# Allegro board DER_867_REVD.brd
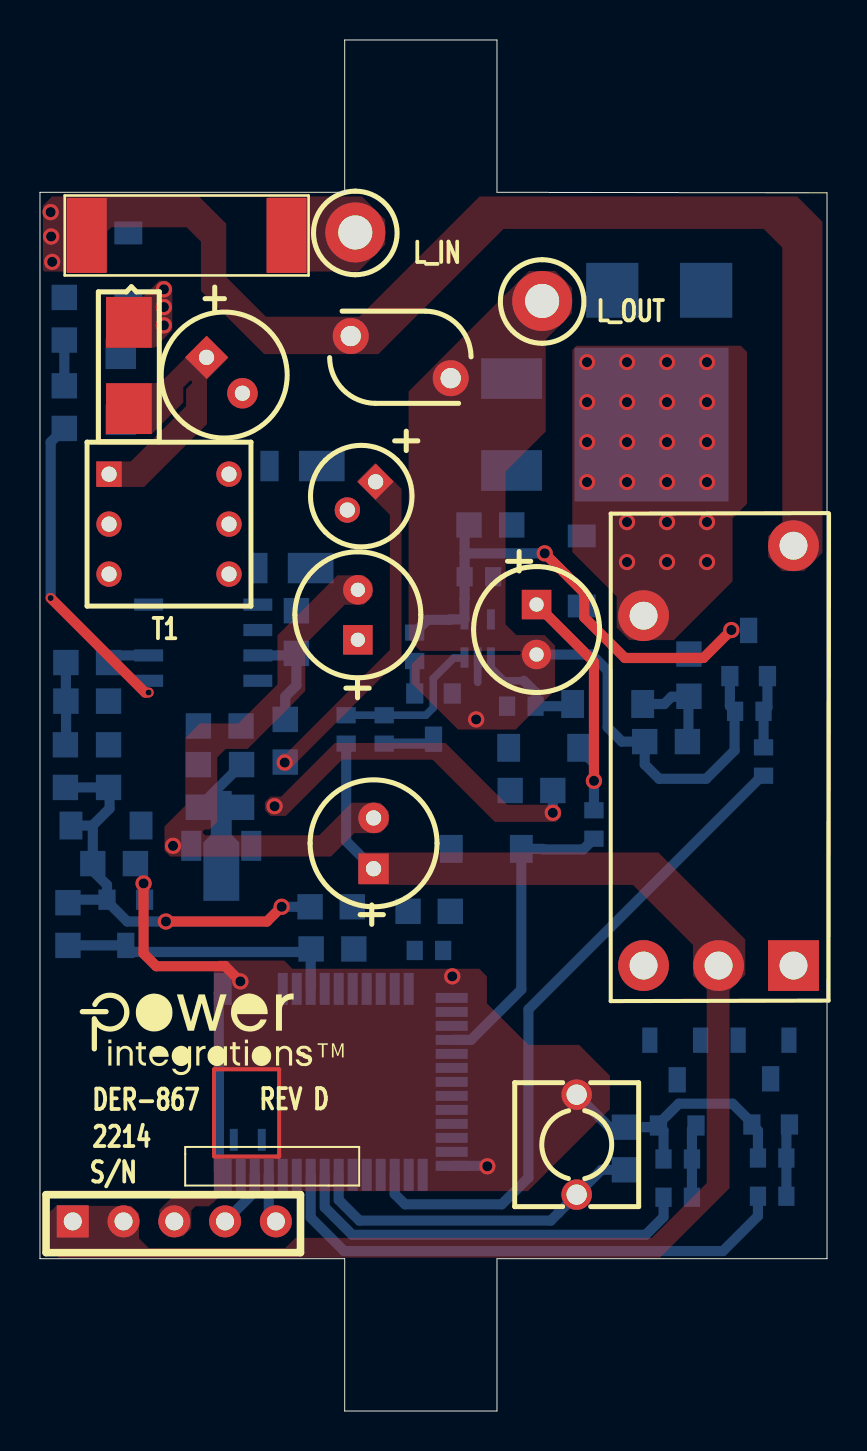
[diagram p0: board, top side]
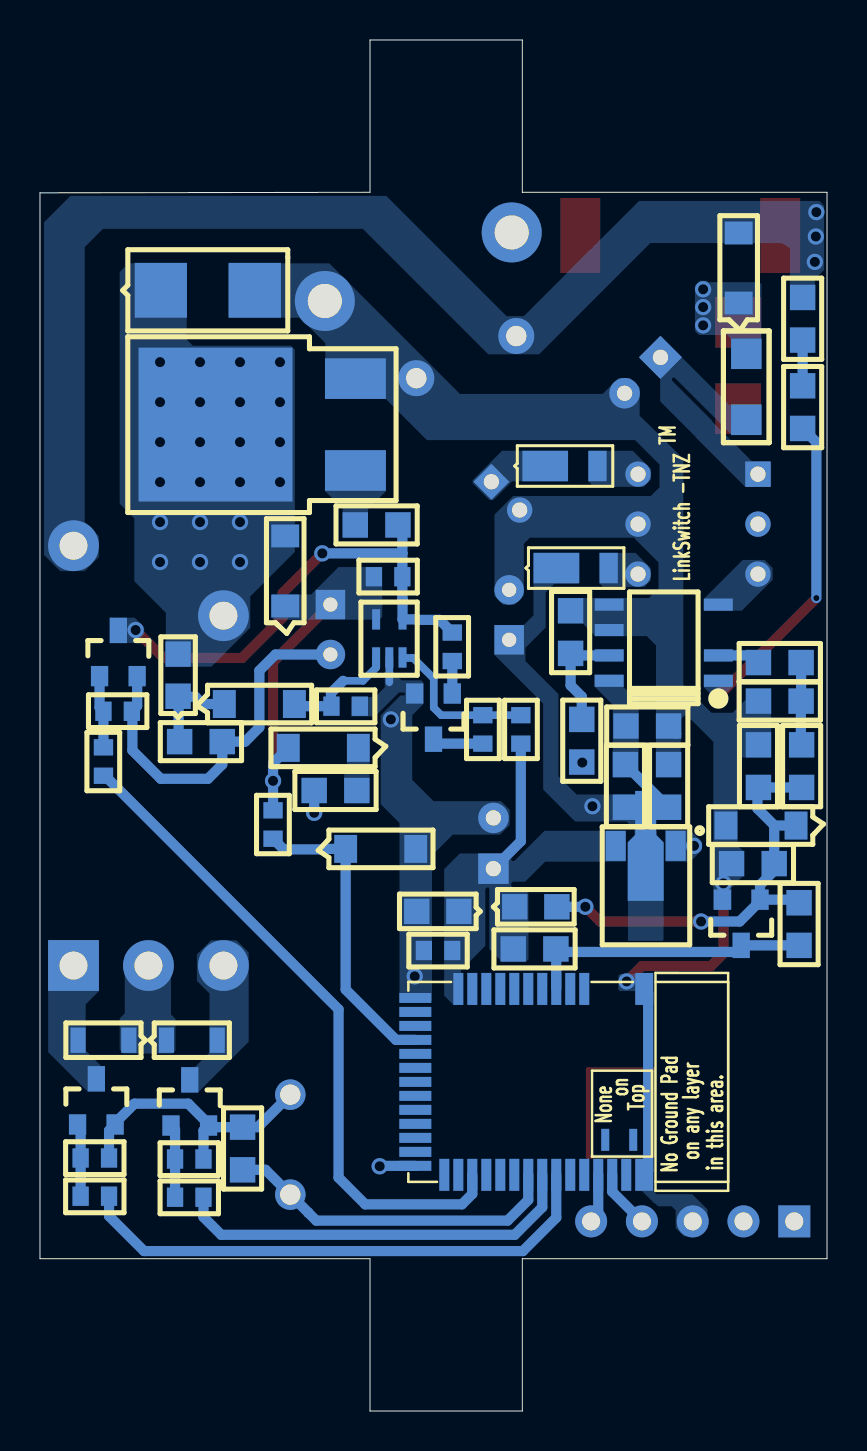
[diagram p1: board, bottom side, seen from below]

Outline 39.37 x 68.58 mm; copper layers: TOP, BOTTOM. Coordinates in mm from the lower left corner of the outline.
Outline path: 0,60.96 0,7.62 15.24,7.62 15.24,0 22.86,0 22.86,7.62 39.37,7.62 39.37,60.93 22.86,60.96 22.86,68.58 15.24,68.58 15.24,60.96 0,60.96

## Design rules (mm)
constraint set DEFAULT: min track width 0.508

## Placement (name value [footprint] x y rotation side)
C1  2.2 uF  [PIPOLCAP6P3X16P5D030]  8.33 52.7 315 top
C5  100 nF  [PISMC0805]  12.83 37.9 90 bottom
C6  56 uF  [PIPOLCAPCLYD200LS80030]  16.79 46.48 225 top
C7  10 uF  [PISMC0603]  20.17 23.04 180 bottom
C8  100 pF  [PISMC0805]  1.3 35.51 0 bottom
C9  100 nF  [PISMC0805]  29.24 12.07 90 bottom
C12  100 nF  [PISMC0805]  30.25 33.48 0 bottom
C13  100 uf  [PIPOLCAPCLYD248LS098028]  24.84 39.09 270 top
C14  220 uF  [PIPOLCAPCLYD248LS098028]  15.9 39.83 90 top
C15  560 uF  [PIPOLCAPCYLD250LS100030]  16.69 27.13 90 top
C16  100 nF  [PISMC0805]  10.06 34.26 180 bottom
C17  100 pF  [PISMC0805]  3.43 31.19 90 bottom
D1  DFLS160-7  [PISMDDFLR120012]  13.56 42.16 0 bottom
D2  S1V-13-F  [PI_SM_SOD-123_12]  4.42 55.42 90 bottom
D3  DFLR1200-7  [PISMDDFLR120012]  14.12 47.27 0 bottom
D4  1N4148WS  [PISMDSOD323]  18.41 24.99 0 bottom
D7  B340LB-13-F  [PISMDO214AA12]  33.32 56.06 180 bottom
D8  SM4003PL-TP  [PI_SM_SOD-123_12]  27.1 40.27 90 bottom
D9  1N4148WS  [PISMDSOD323]  32.46 35.75 90 bottom
D10  SM4003PL-TP  [PI_SM_SOD-123_12]  23.44 33.17 0 bottom
D11  BAV16WS-7-F  [PISMSOD323]  34.92 18.55 0 bottom
D12  BAV16WS-7-F  [PISMSOD323]  33.05 18.55 180 bottom
D13  DNP  [PISMDSOD323]  15.62 25.22 180 bottom
F1  10 A  [PISMFUSE10P1X3P0]  2.34 58.8 0 top
J1  CON5  [PI_HDRF_1X5_HIROSE]  1.64 9.49 0 top
NOREF  -  []  0 7.62 90 top
NOREF#2  -  []  0 60.96 0 top
NOREF#3  -  []  15.24 0 90 top
NOREF#4  -  []  2.01 21.36 0 top
NOREF#5  -  []  15.24 68.58 0 top
NOREF#6  -  []  -228.6 -137.16 0 top
NOREF#7  -  []  -150.78 61.85 0 top
Q1  IPD036N04LGATMA1  [PISMDDPAK]  23.59 47.04 90 bottom
Q2  MMBT3904  [PISMSOT23123_1]  34.51 36.76 180 bottom
Q3  MMBT3904  [PISMSOT23123_1]  20.62 35.89 0 bottom
Q4  MMBT6427-7-F  [PISMSOT23123_1]  35.61 14.33 180 bottom
Q5  MMBT6427-7-F  [PISMSOT23123_1]  30.94 14.28 180 bottom
Q6  2N7002L  [PISMSOT23123_1]  5.23 25.58 0 bottom
R1  16 K  [PISMR1206]  4.04 49.58 90 bottom
R5  9.31 k  [PISMR0805]  10.08 30.2 90 bottom
R7  17.8 k  [PISMR0805]  7.92 32.33 270 bottom
R8  0.0  [PISMR0805]  3.43 37.44 180 bottom
R9  100 k  [PISMR0603]  27.71 30.05 270 bottom
R10  499 k  [PISMR0805]  1.22 55.7 270 bottom
R11  100 k  [PISMR0603]  34.77 35 0 bottom
R12  47  [PISMR0805]  23.6 44.32 180 bottom
R13  2 k  [PISMR0603]  21.24 41.73 0 bottom
R14  100 k  [PISMR0603]  18.75 38.94 270 bottom
R15  15 k  [PISMR0603]  17.22 33.38 90 bottom
R16  10 k  [PISMR0603]  15.32 33.38 90 bottom
R17  634 k  [PISMR0603]  24.79 35.26 180 bottom
R18  47  [PISMR0805]  23.52 31.04 0 bottom
R19  1 k  [PISMR0603]  37.34 10.74 180 bottom
R20  470 k  [PISMR0603]  37.34 12.66 180 bottom
R21  1 k  [PISMR0603]  32.61 10.69 180 bottom
R22  470 k  [PISMR0603]  32.61 12.61 180 bottom
R24  1 k  [PISMR0603]  36.2 33.2 270 bottom
R25  0.0  [PISMR0805]  1.27 33.32 270 bottom
R26  49.9 k  [PISMR0805]  12.27 34.59 270 bottom
R27  499 k  [PISMR0805]  1.22 51.28 270 bottom
R28  100 k  [PISMR0805]  15.7 23.11 180 bottom
R29  499 k  [PISMR0805]  2.64 27.38 0 bottom
R30  0  [PISMR0805]  1.4 23.29 90 bottom
RL1  SPST NO  [PI_RLY-PANASONIC_2COIL]  37.69 22.28 90 top
RV1  275 Vac  [PI_DISC276X181_LS200X83D040]  15.54 53.77 0 top
SW1  SPST  (NO)  [PI_SWITCH_SPST_TL59]  26.85 13.32 180 top
T1  EE8.3  [PI_BOBBIN_EE8_3_V6P]  3.45 46.86 0 top
TP1  RED  [PITPKEYSTONE125X125]  15.77 58.95 0 top
TP2  RED  [PITPKEYSTONE125X125]  25.12 55.52 0 top
U1  LNK3302D  [PISMSO8_NOP3]  5.44 36.53 90 bottom
U4  MDBT42Q  [PI_MOD_RAYTAC_MDBT42Q]  9.14 21.46 270 bottom
U6  TLV1701AIDCKT  [PISMSC705]  22.56 37.69 180 bottom
U7  MCP1703T-3002E/MB  [PI_SM_SOT89-3]  7.57 28.27 0 bottom
VR1  SMAZ12-13-F  [PISMDO214AC12]  4.45 54.46 270 top
VR2  MMSZ4683T1G  [PI_SM_SOD-123_12]  24.08 28.12 180 bottom
VR3  MMSZ4693T1G  [PI_SM_SOD-123_12]  30.15 35.36 180 bottom
VR4  MMSZ4693T1G  [PI_SM_SOD-123_12]  1.55 29.29 0 bottom

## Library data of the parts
C1 = CAP POL: alternate symbols: (pipolcap6p3x16p5d030H)
C5 C8 C9 C16 C17 = CAP NP
C6 C15 = CAP POL
C7 = CAP NP: room: 3
C12 = CAP NP: room: 1
C13 = CAP POL: alternate symbols: (pipolcapclyd248ls098028_h)
C14 = CAP POL: alternate symbols: (pipolcapclyd6p3x9mm_h)
D1 = DIODE SCHOTTKY
D2 D3 D8-D10 = DIODE
D4 D11-D13 = DIODE: room: 2
D7 = DIODE SCHOTTKY: room: 1
F1 = FUSE
J1 = CON5
Q1 = FET_N_GDS: alternate symbols: (pi_sm_d_pak_1); room: 1
Q2 Q3 = NPN_BEC: room: 1
Q4 Q5 = NPN DAR_BEC: room: 2
Q6 = FET_N_GSD
R1 = R: alternate symbols: (pismr1206_1)
R5 R7 R26 R28 R30 = R
R8 = R: alternate symbols: (pismr0805_1); tolerance: 1%
R9 R19-R22 = R: room: 2
R10-R12 R14-R18 R24 R27 = R: room: 1
R13 = R: alternate symbols: (pismr0603_1); room: 1
R25 = R: alternate symbols: (pismr0805_1)
R29 = R: tolerance: 1%
RL1 = RELAY SPST_PANASONIC_DOUBLECOIL: room: 2
RV1 = VARISTOR
SW1 = SW SPST
T1 = BEE8_3_6P
TP1 TP2 = TESTPOINT: room: 2
U1 = LNK-TNZ
U4 = Mod_Raytac_MDBT42Q
U6 = TLV1701a
U7 = LM78LXX_GIO
VR1 VR3 VR4 = DIODE_ZENER
VR2 = DIODE_ZENER: room: 3

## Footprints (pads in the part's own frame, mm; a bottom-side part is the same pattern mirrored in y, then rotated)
PI_BOBBIN_EE8_3_V6P
  rect 1.27x1.27 hole 0.762: 1(0,0)
  round 1.27 hole 0.762: 2(0,-2.5) 3(0,-5) 4(6,-5) 5(6,-2.5) 6(6,0)
PI_DISC276X181_LS200X83D040
  round 1.8 hole 1.016: 1(0,0) 2(5.001,-2.108)
PI_HDRF_1X5_HIROSE
  rect 1.6x1.6 hole 0.9: 1(0,0)
  round 1.6 hole 0.9: 2(2.54,0) 3(5.08,0) 4(7.62,0) 5(10.16,0)
PI_MOD_RAYTAC_MDBT42Q
  rect 1.6x0.899 smd: 1(0.35,0) 39(9.65,0)
  rect 1.6x0.5 smd: 2(0.35,-3) 3(0.35,-3.7) 4(0.35,-4.4) 5(0.35,-5.1) 6(0.35,-5.8) 7(0.35,-6.5) 8(0.35,-7.2) 9(0.35,-7.9) 10(0.35,-8.6) 11(0.35,-9.3) 25(9.65,-10) 26(9.65,-9.3) 27(9.65,-8.6) 28(9.65,-7.9) 29(9.65,-7.2) 30(9.65,-6.5) 31(9.65,-5.8) 32(9.65,-5.1) 33(9.65,-4.4) 34(9.65,-3.7) 35(9.65,-3) 36(9.65,-2.3) 37(9.65,-1.6) 38(9.65,-0.9)
  rect 0.5x1.6 smd: 12(0.8,-11.45) 13(1.5,-11.45) 14(2.2,-11.45) 15(2.9,-11.45) 16(3.6,-11.45) 17(4.3,-11.45) 18(5,-11.45) 19(5.7,-11.45) 20(6.4,-11.45) 21(7.1,-11.45) 22(7.8,-11.45) 23(8.5,-11.45) 24(9.2,-11.45)
  rect 1.1x0.399 smd: 40(7.9,-0.55) 41(7.9,-1.95)
PI_RLY-PANASONIC_2COIL
  rect 2.54x2.54 hole 1.397: 1(0,0)
  round 2.54 hole 1.397: 3(21.001,0) 5(17.501,7.501) 6(0,7.501) 7(0,3.749)
PI_SM_SOD-123_12
  rect 1.143x1.397 smd: 1(0,0) 2(3.505,0)
PI_SM_SOT89-3
  rect 1.001x1.501 smd: 1(0,0) 3(3,0)
  custom 0.45x0.45 smd: 2(1.501,0)
PI_SWITCH_SPST_TL59
  round 1.524 hole 1.016: 1(0,-2.5) 2(0,2.5)
PIPOLCAP6P3X16P5D030
  rect 1.524x1.524 hole 0.762: 1(0,0)
  round 1.524 hole 0.762: 2(2.54,0)
PIPOLCAPCLYD200LS80030
  rect 1.27x1.27 hole 0.762: 1(0,0)
  round 1.27 hole 0.762: 2(2,0)
PIPOLCAPCLYD248LS098028
  rect 1.473x1.473 hole 0.711: 1(-1.25,0)
  round 1.473 hole 0.711: 2(1.25,0)
PIPOLCAPCYLD250LS100030
  rect 1.524x1.524 hole 0.762: 1(0,0)
  round 1.524 hole 0.762: 2(2.54,0)
PISMC0603
  rect 0.813x0.965 smd: 1(0,0) 2(1.422,0)
PISMC0805
  rect 1.27x1.27 smd: 1(0,0) 2(2.134,0)
PISMDDFLR120012
  rect 2.286x1.524 smd: 1(-0.025,0)
  rect 0.914x1.524 smd: 2(-2.642,0)
PISMDDPAK
  rect 2.032x3.048 smd: 1(0.005,0) 3(4.6,0)
  rect 7.699x7.699 smd: 2(2.301,7)
PISMDO214AA12
  rect 2.616x2.743 smd: 1(0,0) 2(4.699,0)
PISMDO214AC12
  rect 2.54x2.286 smd: 1(0,0) 2(4.318,0)
PISMDSOD323
  rect 1.27x1.27 smd: 1(0,0) 2(2.108,0)
PISMFUSE10P1X3P0
  rect 2x3.75 smd: 1(0,0) 2(10,0)
PISMR0603
  rect 0.813x0.965 smd: 1(0,0) 2(1.422,0)
PISMR0805
  rect 1.27x1.27 smd: 1(0,0) 2(2.134,0)
PISMR1206
  rect 1.524x1.524 smd: 1(0,0) 2(3.302,0)
PISMSC705
  rect 0.399x1.016 smd: 1(0,0) 2(0.66,0) 3(1.321,0) 4(1.321,1.905) 5(0,1.905)
PISMSO8_NOP3
  rect 0.61x1.448 smd: 1(0,0) 2(1.27,0) 4(3.81,0) 5(3.81,5.461) 6(2.54,5.461) 7(1.27,5.461) 8(0,5.461)
PISMSOD323
  rect 0.762x1.27 smd: 1(0,0) 2(2.54,0)
PISMSOT23123_1
  rect 0.864x1.016 smd: 1(-1.88,0) 2(0,0)
  rect 0.864x1.27 smd: 3(-0.94,2.286)
PITPKEYSTONE125X125
  round 3 hole 1.702: 1(0,0)

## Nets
3V: C7.2 C15.1 D4.1 D11.1 D12.1 D13.1 J1.1 J1.2 R16.1 R28.1 RL1.7 U4.11(VDD) U7.3(OUT)
ADC_STATUS: C13.1 D8.1 D10.2 R9.1 R13.2 U6.5
L_IN: F1.2 TP1.1
L_OUT: C1.2 C5.2 C6.2 C7.1 C8.2 C9.2 C12.1 C13.2 C14.2 C15.2 C16.2 C17.2 D4.2 D7.2 J1.3 Q1.3(S) Q2.2(EMITTER) Q3.2(EMITTER) Q4.2(E) Q5.2(E) Q6.2(S) R7.1 R11.1 R17.2 R20.2 R22.2 R29.2 RV1.2 SW1.1 T1.5 TP2.1 U1.5 U1.6 U4.1 U4.12 U4.24 U4.39 U6.2 U7.1 VR2.2 VR4.2
LDO_IN: C14.1 D1.1 R5.1 R18.2 U7.2
ON_OFF: C9.1 SW1.2 U4.31
RLY_OFF: R19.2 U4.33
RLY_ON: R21.2 U4.32
STATUS_ADC: R9.2 U4.15 VR2.1
SWDCLK: J1.5 U4.36
SWDIO: J1.4 U4.37
ZCD_IN: Q6.3 R28.2 R30.1 U4.4
ZCD_OUT: R24.2 U4.27
N48269: D7.1 D8.2 D9.2 Q1.2 RL1.5
N49650: R17.1 U6.1 VR3.2
N51578: Q2.3 R12.2 R13.1 R14.1 U6.4
N257317: R15.2 R16.2 U6.3
N372848: D11.2 Q4.3 RL1.1
N372944: D12.2 Q5.3 RL1.6
N414217: Q1.1 R12.1
N423761: Q5.1 R21.1 R22.1
N460853: D10.1 R18.1
N471353: C12.2 D9.1 VR3.1
N477862: Q2.1 R11.2 R24.1
N518037: Q3.3 R15.1
N525361: Q4.1 R19.1 R20.1
N526799: Q3.1 R14.2
N595771: D2.2 F1.1 R10.1 RL1.3(NO) RV1.1
N598020: C1.1 R1.1 T1.1 VR1.2
N632777: R10.2 R27.1
N682309: R27.2 U1.1
N682418: T1.3 U1.4
N687847: D3.2 T1.6
N687859: C6.1 D3.1 R26.2
N687971: D1.2 T1.4
N688873: C16.1 R5.2 R7.2 U1.8
N704755: C5.1 R26.1 U1.7
N705901: C17.1 D13.2 Q6.1 R25.2 R29.1 R30.2 VR4.1
N724784: R8.1 U1.2
N755538: C8.1 R8.2 R25.1
N772684: D2.1 R1.2 VR1.1

Pads without a net: T1 2; U4 2 3 5 6 7 8 9 10 13 14 16 17 18 19 20 21 22 23 25 26 28 29 30 34 35 38 40 41

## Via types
v1: diameter 0.813, hole 0.508, TOP to BOTTOM, 42 vias
v2: diameter 0.457, hole 0.305, TOP to BOTTOM, 2 vias

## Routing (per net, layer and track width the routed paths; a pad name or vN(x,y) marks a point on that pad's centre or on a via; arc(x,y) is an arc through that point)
3V: length 7.6
  BOTTOM w0.508: C15.1 15.32,28.5 R16.1 ; 34.47,22.81 RL1.7
ADC_STATUS: length 13.4
  TOP w0.508: v1(27.71,31.52) 27.71,37.47 C13.1
  BOTTOM w0.508: R9.1 v1(27.71,31.52) 27.71,32.41 D10.2
L_OUT: length 55.2
  TOP w0.508: v1(5.18,26.39) 5.18,22.89 5.82,22.25 9.26,22.25 v1(10.02,21.49)
  BOTTOM w0.381: U6.2 21.89,36.45
  BOTTOM w0.508: Q5.2 30.94,14.36 31.95,15.37 34.65,15.37 35.61,14.41 Q4.2 35.92,14.03 R20.2 ; Q5.2 31.19,14.03 R22.2 ; Q5.2 30.85,14.2 C9.2 28.47,14.2 SW1.1 ; C16.2 7.54,33.88 ; v1(22.38,12.24) 22.36,12.26 U4.24 ; C13.2 27.59,37.84 28.4,37.03 28.4,34.2 29.11,33.48 C12.1 30.25,32.34 30.97,31.62 33.32,31.62 34.75,33.05 34.75,34.98 R11.1 34.51,35.26 Q2.2 ; U4.1 8.95,20.92 8.95,12.01 U4.39
  vias: v1(6.65,28.27) v1(20.62,21.74) v1(21.82,34.59)
LDO_IN: length 1.1
  BOTTOM w0.508: v1(25.65,29.92) R18.2
  vias: v1(11.73,30.25)
ON_OFF: length 17
  BOTTOM w0.508: C9.1 28.09,12.07 SW1.2 25.95,9.93 25.95,9.92 25.55,9.53 15.98,9.53 14.94,10.56 U4.31
RLY_OFF: length 26.9
  BOTTOM w0.508: R19.2 35.92,9.75 34.16,8 15.21,8 13.54,9.67 U4.33
RLY_ON: length 20.5
  BOTTOM w0.508: U4.32 14.24,10.19 15.62,8.81 30.3,8.81 31.19,9.7 R21.2
STATUS_ADC: length 15.4
  BOTTOM w0.508: R9.2 27.18,28.09 25.18,28.09 25.16,28.12 VR2.1 24.08,21.08 21.56,18.56 U4.15
SWDCLK: length 2.5
  BOTTOM w0.508: J1.5 11.44,9.84 U4.36
SWDIO: length 2.9
  BOTTOM w0.508: J1.4 10.74,10.97 U4.37
ZCD_IN: length 14.3
  BOTTOM w0.508: R28.2 13.54,23.09 ; 13.54,23.09 U4.4 ; 13.54,23.09 13.41,22.96 4.62,22.96 Q6.3 R30.1
ZCD_OUT: length 33.4
  BOTTOM w0.508: U4.27 17.74,10.86 18.26,10.34 23.1,10.34 24.43,11.68 24.43,20.09 36.12,31.78 R24.2
N48269:
  vias: v1(27.36,52.47) v1(27.36,50.47) v1(27.36,48.47) v1(27.36,46.47) v1(29.36,52.47) v1(29.36,50.47) v1(29.36,48.47) v1(29.36,46.47) v1(29.36,44.47) v1(29.36,42.47) v1(31.36,52.47) v1(31.36,50.47) v1(31.36,48.47) v1(31.36,46.47) v1(31.36,44.47) v1(31.36,42.47) v1(33.36,52.47) v1(33.36,50.47) v1(33.36,48.47) v1(33.36,46.47) v1(33.36,44.47) v1(33.36,42.47)
N49650: length 5.9
  BOTTOM w0.381: 24.21,36.53 23.22,36.53 22.56,37.19 U6.1
  BOTTOM w0.508: VR3.2 26.54,35.26 R17.1 24.82,35.28 24.82,35.92 24.21,36.53
N51578: length 24.4
  TOP w0.508: v1(25.25,42.9) 27.23,40.92 27.23,39.7 29.26,37.67 33.19,37.67 v1(34.59,39.07)
  BOTTOM w0.508: v1(25.25,42.9) 21.24,42.9 21.24,42.9 ; 21.24,42.9 21.24,44.1 21.46,44.32 ; 21.24,42.9 R13.1 21.24,40.62 21.23,40.61 U6.4 20.53,39.6 20.5,39.57 19.38,39.57 R14.1
N257317: length 8
  BOTTOM w0.381: U6.3 21.21,37.67 20.7,37.67 19.67,36.64 19.67,35.18 19.3,34.8 R15.2 R16.2
N423761: length 3.7
  BOTTOM w0.508: Q5.1 32.61,14.08 R22.1 R21.1
N471353: length 4.7
  BOTTOM w0.508: C12.2 32.44,33.53 32.44,35.73 ; 32.44,35.73 31.59,35.73 31.23,35.36 VR3.1 ; 32.44,35.73 D9.1
N477862: length 3.6
  BOTTOM w0.508: R24.1 R11.2 36.39,35.2 Q2.1
N518037: length 2.6
  BOTTOM w0.508: R15.1 19.46,33.38 19.68,33.6
N525361: length 3.7
  BOTTOM w0.508: R19.1 R20.1 37.34,14.18 Q4.1
N526799: length 1.6
  BOTTOM w0.508: Q3.1 R14.2
N595771:
  vias: v1(0.53,59.97) v1(0.56,58.75) v1(0.61,57.48)
N632777: length 2.3
  BOTTOM w0.508: R27.1 R10.2
N682309: length 15.6
  TOP w0.508: v2(0.53,40.67) 5.26,35.94 v2(5.44,35.94)
  BOTTOM w0.508: R27.2 0.53,48.46 v2(0.53,40.67)
N687859:
  vias: v1(12.24,32.44)
N688873: length 3
  BOTTOM w0.508: R7.2 7.95,30.2 R5.2
N704755: length 5.5
  BOTTOM w0.508: R26.1 12.27,35.74 12.83,36.3 C5.1 12.73,37.8 U1.7
N705901: length 22.5
  TOP w0.508: v1(6.3,24.49) 11.35,24.49 v1(12.09,25.22)
  BOTTOM w0.508: VR4.1 2.63,29.29 ; 2.63,29.29 3.48,30.14 3.48,31.14 C17.1 R25.2 ; 2.63,29.29 2.64,29.27 R29.1 2.64,27.03 3.35,26.31 Q6.1 ; Q6.1 1.55,25.58 1.4,25.43 ; Q6.1 3.35,25.5 4.37,24.49 v1(6.3,24.49) ; D13.2 v1(12.09,25.22)
N724784: length 2.2
  BOTTOM w0.508: R8.1 3.78,37.8 U1.2
N755538: length 4.1
  BOTTOM w0.508: R8.2 C8.1 1.31,35.5 1.31,33.36 R25.1
N772684:
  vias: v1(6.2,56.11) v1(6.2,55.22) v1(6.2,54.31)

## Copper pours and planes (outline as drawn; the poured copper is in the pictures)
3V on TOP: 0.91,7.67 0.51,8.08 0.51,9.98 0.58,10.06 0.61,10.06 0.81,10.26 4.57,10.26 4.95,9.88 4.95,8.64 5.44,8.15 12.27,8.15 12.78,8.66 30.61,8.66 33.35,11.4 33.35,21.08 32.66,21.77 32.66,23.32 29.67,26.31 15.98,26.31 15.93,26.37 15.93,27.89 15.98,27.94 30.94,27.94 35.28,23.6 35.28,21.82 34.49,21.03 34.49,11.15 31.01,7.67
3V on BOTTOM: 35.18,17.88 35.38,18.08 35.38,19.63 35.13,19.89 35.13,22.81 34.54,23.39 33.43,23.39 32.82,22.78 32.82,19.84 32.59,19.61 32.59,18.03 32.74,17.88
3V on BOTTOM: 17.09,23.27 17.09,26.11 17.02,26.19 16.94,26.19 16.89,26.14 16.89,23.11 16.24,22.47 15.06,22.47 14.94,22.59 14.94,25.91 14.96,25.91 15.25,26.2 15.71,26.2 15.8,26.29 15.8,26.39 15.71,26.48 15.1,26.48 14.1,27.48 10.07,27.48 10.07,29.02 14.13,29.02 15.65,27.51 15.75,27.51 15.8,27.56 15.8,27.66 15.61,27.85 15.65,27.89 18.36,27.89 19.15,27.1 19.15,20.78 18.69,20.32 18.31,20.32 18.31,22.05
ADC_STATUS on BOTTOM: 27.81,39.73 27.81,40.79 27.76,40.84 25.81,40.84 24.43,42.21 22.33,42.21 22.25,42.14 22.25,39.72 22.38,39.59 27.67,39.59
L_IN on TOP: 11.4,57 15.93,57 17.27,58.34 17.27,59.59 16.1,60.76 11.47,60.76 11.4,60.68
L_OUT on TOP: 6.23,29.24 7.26,30.28 7.26,33.66 8,34.39 9.93,34.39 11.87,36.33 11.87,38.8 14.88,41.81 16.21,41.81 16.64,41.38 16.64,40.77 16.21,40.34 15.25,40.34 15.04,40.13 13.28,38.37 13.28,37.85 13.27,37.83 13.27,36.02 12.98,35.73 12.98,35.71 10.39,33.12 9.3,33.12 8.86,32.69 8.86,29.46 8.48,29.08 8.23,29.08 8.15,29.01 8.15,28.91 8.26,28.8 13.97,28.8 15.6,30.43 17.02,30.43 17.45,30 17.45,29.34 17.02,28.91 15.72,28.91 14.55,27.74 6.51,27.74 6.23,28.02
L_OUT on TOP: 18.44,51 18.44,38.61 19.02,38.02 23.98,38.02 24.05,37.95 24.05,37.9 23.98,37.82 19.05,37.82 18.59,37.36 18.59,36.55 18.59,36.55 18.59,36.4 20.91,34.09 23.8,34.09 25.77,36.06 25.77,38.29 25.25,38.81 23.83,38.81 23.29,39.34 23.29,46.99 25.3,49 25.3,53.59 26.62,54.91 26.62,56.18 25.78,57.02 24.46,57.02
L_OUT on TOP: 5.97,10.06 6.75,10.84 8.52,10.84 8.71,11.03 8.71,12.69 8.73,12.71 11.97,12.71 11.99,12.73 11.99,17.09 11.96,17.12 8.69,17.12 8.69,22.26 8.96,22.53 12.22,22.53 12.62,22.12 21.97,22.12 22.35,21.74 22.35,20.4 24.43,18.31 26.97,18.31 28.51,16.78 28.51,15.1 24.41,11 9.3,11 9.24,11 8.48,10.24 7.77,10.24 7.57,10.03 7.57,9.14 7.16,8.74 6.4,8.74 5.97,9.17
L_OUT on BOTTOM: 4.15,26.81 4.15,27.97 4.47,28.29 4.47,32.49 4.27,32.69 2.81,32.69 2.79,32.71 2.79,36.12 4.06,36.12 4.06,35.59 4.72,34.92 5.78,34.92 7.19,36.34 7.19,47.62 8.48,48.92 9.37,49.78 9.37,51.21 9.83,51.66 10.44,51.66 11.23,50.88 18.36,50.88 24.89,57.4 29.82,57.4 29.95,57.28 29.95,54.74 29.9,54.69 26.37,54.69 25.1,53.42 25.1,50.7 25.02,50.62 22.07,50.62 20.02,48.56 9.6,48.56 8.38,47.35 8.38,46.2 8.81,45.77 15.7,45.77 16.64,44.83 16.64,40.77 16.21,40.34 15.62,40.34 15.16,40.79 15.16,43.38 14.86,43.69 9.67,43.69 8.43,42.45 8.43,41.15 8.92,40.67 13.46,40.67 13.46,39.4 12.22,39.4 11.58,38.76 9.02,38.76 8.56,38.3 8.56,31.7 8.55,31.7 7.31,31.7 7.3,31.71 7.32,31.73 7.32,34.6 7.14,34.78 6.99,34.78 5.69,33.48 5.69,25.07 4.78,25.07 4.78,26.19
L_OUT on BOTTOM: 8.76,21.87 10.34,21.87 10.44,21.77 10.44,21.08 10.36,21.01 8.89,21.01 8.76,21.13
L_OUT on BOTTOM: 8.08,29.06 8.1,29.03 8.1,27.53 8.05,27.48 6.83,27.48 6.26,28.06 6.26,28.47 6.85,29.06
L_OUT on BOTTOM: 7.77,10.24 7.57,10.03 7.57,9.14 7.16,8.74 6.4,8.74 5.98,9.16 5.98,10.08 6.75,10.85 8.53,10.85 8.7,11.02 8.7,12.61 9.21,12.61 9.39,12.43 9.39,11.14 8.49,10.24
L_OUT on BOTTOM: 19.76,20.52 19.76,27.79 18.72,28.83 16.36,28.83 15.85,29.34 15.85,30.05 16.31,30.51 19.68,30.51 20.75,31.57 20.75,34.8 20.19,35.36 20.19,36.44 20.31,36.55 21.28,36.55 21.76,37.03 22.05,37.03 22.12,36.96 22.12,36.2 22.61,35.71 23.67,35.71 23.68,35.71 23.79,35.71 23.8,35.7 23.8,35.59 23.8,35.59 23.8,34.75 23.8,34.75 23.62,34.75 23.62,34.75 22.61,34.75 21.41,35.94 21.16,35.94 21.11,35.89 21.11,35.84 21.16,35.79 21.34,35.79 22.33,34.8 22.33,30.35 21.39,29.41 21.39,20.52
LDO_IN on TOP: 14.74,33.41 20.28,33.41 23.37,30.33 25.85,30.33 26.07,30.11 26.07,29.72 25.81,29.47 22.75,29.47 19.65,32.58 15.1,32.58 12.29,29.77 11.53,29.77 11.25,30.05 11.25,30.45 11.53,30.73 12.06,30.73
LDO_IN on BOTTOM: 8.18,23.57 8.18,26.47 8.51,26.8 8.51,28.98 9.45,29.92 9.45,30.84 12.52,30.84 13.44,31.75 13.44,35.86 15.09,37.52 15.09,38.18 14.07,39.19 14.07,40.94 13.61,41.4 12.45,41.4 12.4,41.45 12.4,42.93 14.68,42.93 14.68,39.8 15.16,39.32 16.56,39.32 16.64,39.24 16.64,37.82 14.2,35.38 14.2,31.09 12.6,29.49 10.03,29.49 9.63,29.08 9.63,26.8 9.96,26.47 9.96,23.55 9.93,23.52 8.23,23.52
N48269 on TOP: 26.63,42.96 26.63,53.08 26.84,53.28 35.06,53.28 35.38,52.97 35.38,45.39 34.64,44.66 34.64,41.5 31.71,38.56 29.48,38.56 28.85,39.19 28.85,40.74
N48269 on BOTTOM: 26.62,53.09 26.62,42.98 28.85,40.74 28.85,39.17 30.79,37.24 33.07,37.24 33.07,39.93 34.65,41.5 34.65,44.65 35.38,45.39 35.38,56.97 34.95,57.4 32.18,57.4 32.03,57.25 32.03,53.59 31.72,53.29 26.82,53.29
N51578 on BOTTOM: 35.88,39.68 35.88,38.42 34.61,38.42 34.16,38.87 34.16,39.21 34.63,39.68
N372848 on BOTTOM: 36.14,17.25 36.3,17.25 37.08,18.03 37.08,20.35 36.42,21.01 36.42,23.5 36.47,23.55 38.94,23.55 38.96,23.52 38.96,17.96 36.98,15.98 36.17,15.98 36.12,16.03 36.12,17.22
N372944 on BOTTOM: 32.26,17.2 31.62,17.2 30.89,17.93 30.89,20.88 31.52,21.51 31.52,22.83 30.81,23.55 29.54,23.55 28.93,22.94 28.93,18.47 31.47,15.93 32.28,15.93 32.31,15.95 32.31,17.14
N414217 on BOTTOM: 24.23,43.69 22.96,43.69 22.96,43.69 22.96,45.11 22.07,46.01 22.07,48.06 22.07,48.06 25.11,48.06 25.11,46.02 24.23,45.14
N460853 on BOTTOM: 24.05,30.4 24.16,30.51 24.16,31.95 24.02,32.09 24.02,33.77 23.93,33.86 23.01,33.86 22.89,33.73 22.89,30.53 23.01,30.4
N595771 on TOP: 37.13,44.48 37.13,58.19 36.2,59.13 23.19,59.13 16.93,52.87 11.21,52.87 8.05,56.03 8.05,58.5 7.34,59.21 3.57,59.21 3.38,59.02 3.38,57 3.38,57 0.22,57 0.15,57.06 0.15,60.3 0.61,60.76 7.95,60.76 9.32,59.39 9.32,56.72 11.3,54.74 15.98,54.74 22,60.76 37.87,60.76 39.14,59.49 39.14,42.93 38.23,42.01 37.13,42.01 36.42,42.72 36.42,43.76
N595771 on BOTTOM: 37.13,42.01 36.42,42.72 36.42,43.76 37.13,44.48 37.13,58.22 36.22,59.13 23.22,59.13 16.94,52.86 14.4,52.86 8.84,58.42 2.26,58.42 1.85,58.17 1.85,55.09 1.83,55.07 0.61,55.07 0.61,56.62 0.15,57.07 0.15,60.3 0.38,60.53 9.4,60.53 15.16,54.76 16.03,54.76 22.05,60.78 37.85,60.78 39.17,59.46 39.17,42.82 38.35,42.01
N598020 on TOP: 2.82,46.23 2.82,47.5 4.54,47.5 7.31,50.27 7.31,51.12 7.6,51.41 7.6,51.51 7.57,51.54 7.5,51.54 7.17,51.2 7.17,50.45 5.59,48.87 3.3,48.87 3.3,51.43 3.31,51.42 6.01,51.42 8.36,53.77 9.42,52.7 9.42,52.65 8.35,51.58 8.35,49.37 5.21,46.23
N598020 on BOTTOM: 2.79,46.3 2.79,47.42 2.87,47.5 3.74,47.5 5.75,49.51 5.75,49.54 7.76,51.54 7.76,51.63 7.7,51.69 7.63,51.69 4.75,48.82 3.3,48.82 3.25,48.87 3.25,50.29 3.3,50.34 4.9,50.34 8.31,53.75 8.36,53.75 9.37,52.73 9.37,52.68 8.35,51.66 8.35,50.51 6.58,48.74 6.58,48.71 4.1,46.23 2.87,46.23
N682309 on BOTTOM: 4.71,36.82 4.71,36.24 5.27,35.68 5.64,35.68 6.16,36.2 6.16,36.81 6.14,36.82 4.72,36.82
N682418 on BOTTOM: 2.72,41.58 4.27,40.03 6.12,40.03 6.17,40.08 6.17,40.61 4.22,42.57 3.12,42.57 2.72,42.16
N687847 on BOTTOM: 11.66,46.23 9.17,46.23 8.8,46.6 8.8,47.12 9.72,48.03 11.94,48.03 11.94,46.51
N687859 on TOP: 16.81,47.4 18.08,46.13 18.08,37.69 12.42,32.03 12.09,32.03 11.84,32.28 11.84,32.61 12.12,32.89 12.32,32.89 17.5,38.07 17.5,44.83 15.88,46.46 15.88,46.53 16.74,47.4
N687859 on BOTTOM: 16.26,48.03 17.73,46.56 17.73,46.41 16.89,45.57 16.69,45.57 15.75,46.51 12.95,46.51 12.95,48.03
N687971 on BOTTOM: 11.38,42.93 11.38,41.4 11.2,41.22 9.14,41.22 8.81,41.55 8.81,42.16 9.58,42.93
N688873 on BOTTOM: 10.19,36.83 10.19,36.22 9.42,35.46 9.42,31.72 9.45,31.7 10.69,31.7 10.72,31.72 10.72,35.33 11.63,36.25 11.63,36.83
N772684 on TOP: 6.34,56.54 5.96,56.54 5.15,55.73 3.3,55.73 3.3,53.19 5.75,53.19 6.62,54.06 6.62,56.26
N772684 on BOTTOM: 3.28,52.2 3.28,56.36 3.38,56.46 5.94,56.46 6.02,56.54 6.35,56.54 6.6,56.29 6.6,54.03 6.4,53.82 4.98,53.82 4.8,53.64 4.8,52.2 4.72,52.12 3.35,52.12

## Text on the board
Ref Des/Silkscreen Bottom: LinkSwitch -TNZ | TM
Ref Des/Silkscreen Top: S/N | DER-867 | 2214 | REV D | L_IN | L_OUT
User.6: 14.  FAB HOUSE LOGO,DATE CODE TO BE IN SILK SCREEN ONLY.DO NOT USE COPPER. | 13.  MATERIAL FR4 COPPER 2oz THICKNESS 0.062" | PLEASE DELETE THIS PIN
User.9: FIGURE | FINISHED_SIZE | 12.0 | 20.0 | 28.0 | 30.0 | 35.429 | 40.0 | 55.0 | 67.0 | 125.0 | DRILL CHART: TOP to BOTTOM | ALL UNITS ARE IN MILS | TOLERANCE_DRILL | +3.0/-3.0 | +0.0/-0.0 | PLATED | QTY | 2 | 42 | 4 | 10 | 1 | 5
